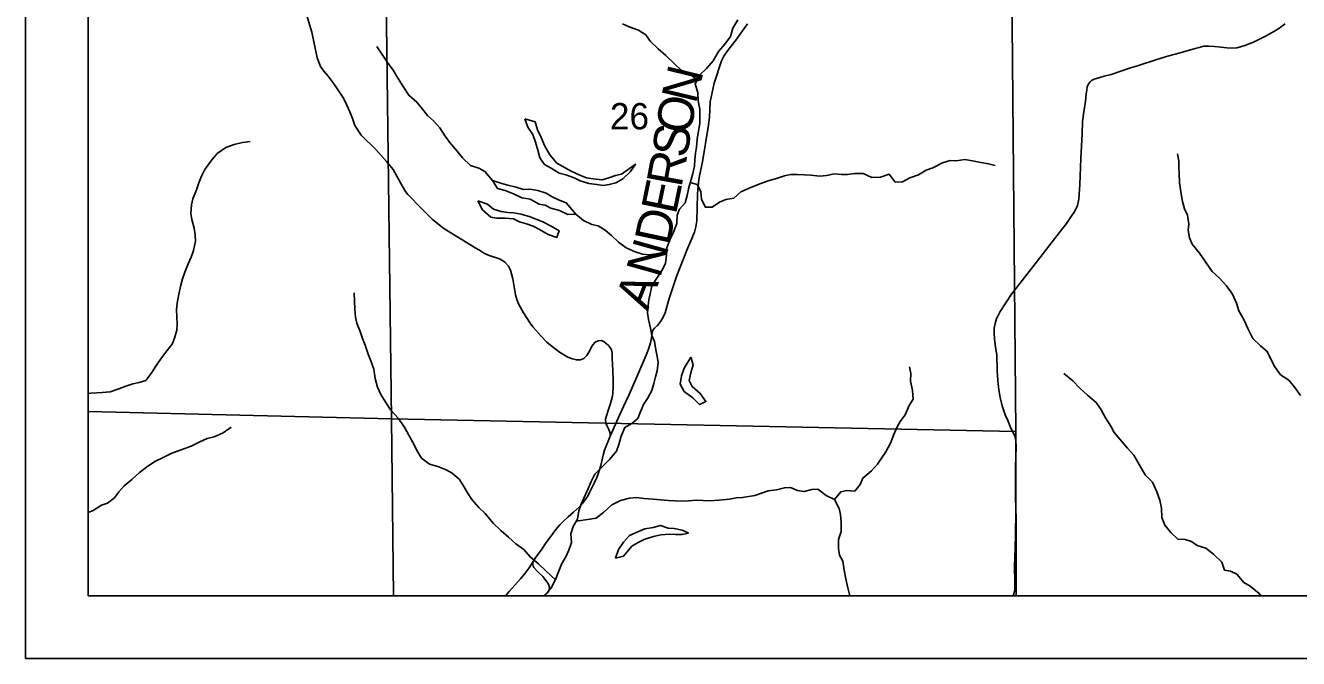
# Model space of a CAD drawing. Extents: x 0 to 34, y 0 to 22.
# Drawn here: x 2 to 4.027, y 14 to 15.007 of the extents above; entities that cross this region are included whole.
import ezdxf

# ---------------------------------------------------------------- set-up
doc = ezdxf.new("R2010")
doc.units = 0
for name, color, linetype in [('Default', 7, 'Continuous'), ('GM_X_Minor_Lake', 7, 'Continuous'), ('GM_X_Minor_River', 7, 'Continuous'), ('GM_X_Rail_Line', 7, 'Continuous'), ('GM_X_Section', 7, 'Continuous'), ('GM_X_Section_Text', 7, 'Continuous'), ('GM_X_Township_Road', 7, 'Continuous'), ('GM_X_Township_Road_Text', 7, 'Continuous'), ('SH_Cut_Line', 7, 'Continuous'), ('SH_Data', 7, 'Continuous')]:
    doc.layers.add(name, color=color, linetype=linetype)

msp = doc.modelspace()

# ---------------------------------------------------------------- linework, layer by layer
at = {"layer": 'Default'}
for points in [[(2.1, 15.3991), (2.1, 14.393), (2.5826, 14.3817), (2.5698, 15.3877)], [(2.1, 14.393), (2.1, 14.1), (2.5857, 14.1), (2.5826, 14.3817)], [(2.5857, 14.1), (3.5773, 14.1), (3.5764, 14.3611), (2.5826, 14.3817)]]:
    msp.add_lwpolyline(points, close=True, dxfattribs=at)
at = {"layer": 'GM_X_Minor_Lake'}
for points in [[(2.7949, 14.8587), (2.7995, 14.8455), (2.8075, 14.8338), (2.8117, 14.8216), (2.8155, 14.8088), (2.8189, 14.797), (2.8262, 14.7864), (2.8368, 14.7804), (2.8497, 14.7725), (2.8603, 14.7695), (2.8736, 14.765), (2.8831, 14.7601), (2.8967, 14.756), (2.9096, 14.7541), (2.9194, 14.753), (2.9293, 14.7542), (2.9399, 14.7572), (2.9512, 14.7633), (2.9629, 14.7747), (2.967, 14.7804)], [(2.967, 14.7804), (2.9712, 14.7865), (2.9614, 14.7796), (2.9489, 14.7709), (2.9391, 14.7686), (2.9289, 14.7651), (2.9183, 14.7617), (2.9035, 14.7636), (2.8929, 14.7647), (2.8823, 14.7692), (2.8686, 14.7756), (2.8591, 14.7809), (2.8459, 14.7884), (2.8345, 14.8016), (2.8268, 14.8152), (2.8211, 14.8289), (2.815, 14.8414), (2.8116, 14.8539), (2.7949, 14.8587)], [(2.7433, 14.7608), (2.7513, 14.7479), (2.7634, 14.7446), (2.7771, 14.7397), (2.79, 14.7333), (2.8036, 14.731), (2.8176, 14.7231), (2.8271, 14.7213), (2.8366, 14.7167), (2.8499, 14.713), (2.8635, 14.7066), (2.876, 14.707)], [(2.876, 14.707), (2.8608, 14.7252), (2.8487, 14.73), (2.8384, 14.7346), (2.8289, 14.7406), (2.8157, 14.7447), (2.8028, 14.747), (2.7929, 14.7466), (2.7812, 14.7499), (2.7679, 14.7533), (2.7581, 14.7559), (2.7433, 14.7608)], [(2.7203, 14.7285), (2.7275, 14.7141), (2.7408, 14.7024), (2.7506, 14.701), (2.7639, 14.701), (2.7768, 14.6999), (2.7863, 14.695), (2.7976, 14.6916), (2.8083, 14.6879), (2.8181, 14.6826), (2.8322, 14.6747), (2.8458, 14.6702), (2.8474, 14.6746)], [(2.8474, 14.6746), (2.8496, 14.6808), (2.8371, 14.6883), (2.8238, 14.6947), (2.8139, 14.6989), (2.8033, 14.703), (2.7893, 14.7071), (2.7775, 14.709), (2.768, 14.7097), (2.7574, 14.7116), (2.7453, 14.7153), (2.7354, 14.7233), (2.7203, 14.7285)], [(3.0593, 14.4798), (3.0487, 14.4623), (3.0446, 14.4498), (3.042, 14.4365), (3.0488, 14.4252), (3.0625, 14.415), (3.0731, 14.404), (3.0777, 14.4063)], [(3.0777, 14.4063), (3.0833, 14.409), (3.0742, 14.4215), (3.0613, 14.4328), (3.0567, 14.4427), (3.0593, 14.4544), (3.0627, 14.4673), (3.0593, 14.4798)], [(3.049, 14.2026), (3.0453, 14.2043), (3.0328, 14.2069), (3.0233, 14.2072), (3.0108, 14.2117), (2.9991, 14.2083), (2.9862, 14.2064), (2.9748, 14.2014), (2.9616, 14.196), (2.9521, 14.1854), (2.9442, 14.1736), (2.9393, 14.1596)], [(2.9393, 14.1596), (2.9522, 14.163), (2.9654, 14.1786), (2.9753, 14.1847), (2.9858, 14.1901), (3.0017, 14.1947), (3.0116, 14.1966), (3.0252, 14.1978), (3.0347, 14.1974), (3.0453, 14.1974), (3.0555, 14.1997), (3.049, 14.2026)]]:
    msp.add_lwpolyline(points, dxfattribs=at)
at = {"layer": 'GM_X_Minor_River'}
for points in [[(2.8887, 14.2553), (2.8947, 14.2678), (2.9007, 14.2815), (2.9064, 14.2933), (2.917, 14.3039), (2.9298, 14.3165), (2.9407, 14.3298), (2.9445, 14.3404), (2.9483, 14.354), (2.9543, 14.3677), (2.9652, 14.3742), (2.9751, 14.3822), (2.9788, 14.3916), (2.9841, 14.4045), (2.9905, 14.414), (2.9969, 14.4266), (3.0003, 14.4379), (3.0029, 14.4482), (3.0055, 14.458), (3.0074, 14.4713), (3.0058, 14.4808), (3.0035, 14.4914), (3.0012, 14.5043), (2.9974, 14.5141), (2.9951, 14.5258), (2.992, 14.5395), (2.9905, 14.5501), (2.9912, 14.5611), (2.9923, 14.5706), (2.9946, 14.5804), (2.9972, 14.5929), (3.0051, 14.6051), (3.0138, 14.618), (3.019, 14.629), (3.0205, 14.6411), (3.0209, 14.6536), (3.0258, 14.6665), (3.0314, 14.6787), (3.037, 14.6923), (3.0374, 14.7056), (3.0412, 14.7151), (3.0502, 14.7253), (3.0532, 14.7367), (3.0562, 14.7496), (3.0596, 14.7621), (3.0622, 14.7716), (3.0648, 14.7837), (3.0655, 14.794), (3.0667, 14.8042), (3.0681, 14.8137), (3.0692, 14.8266), (3.0707, 14.8364), (3.0733, 14.8512), (3.0737, 14.8611), (3.0733, 14.874), (3.071, 14.8876), (3.0702, 14.9005), (3.066, 14.9141), (3.0731, 14.9282), (3.0844, 14.9392), (3.095, 14.951), (3.1033, 14.9658), (3.1131, 14.9775), (3.1222, 14.9901), (3.1263, 15.0033), (3.1338, 15.0166)], [(3.0693, 14.9207), (3.0572, 14.9304), (3.0439, 14.9364), (3.0333, 14.9462), (3.0196, 14.9598), (3.0071, 14.97), (2.9945, 14.9825), (2.9877, 14.9923), (2.9759, 14.9999), (2.9611, 15.0051), (2.9505, 15.01)], [(3.0207, 14.6474), (3.0039, 14.6441), (2.9921, 14.6426), (2.9823, 14.6433), (2.9705, 14.6474), (2.9561, 14.6538), (2.9439, 14.6625), (2.9329, 14.6731), (2.9227, 14.6818), (2.9117, 14.6885), (2.9014, 14.6908), (2.8882, 14.6972), (2.876, 14.707), (2.8635, 14.7066), (2.8499, 14.713), (2.8366, 14.7167), (2.8271, 14.7213), (2.8176, 14.7231), (2.8036, 14.731), (2.79, 14.7333), (2.7771, 14.7397), (2.7634, 14.7446), (2.7513, 14.7479), (2.7433, 14.7608), (2.7315, 14.7748), (2.7216, 14.7804), (2.7084, 14.7846), (2.6958, 14.797), (2.6875, 14.8076), (2.6753, 14.8216), (2.6681, 14.8314), (2.6597, 14.8447), (2.6494, 14.8556), (2.6399, 14.8643), (2.6323, 14.8742), (2.6228, 14.8855), (2.6103, 14.8965), (2.6012, 14.9104), (2.592, 14.9248), (2.5856, 14.9365), (2.5761, 14.9483), (2.5593, 14.974)], [(2.1, 14.4215), (2.1045, 14.4224), (2.1223, 14.4236), (2.1351, 14.4244), (2.1488, 14.429), (2.1597, 14.4332), (2.1707, 14.437), (2.1809, 14.4393), (2.1915, 14.4423), (2.2013, 14.4553), (2.2077, 14.4655), (2.2153, 14.4769), (2.2251, 14.4898), (2.2338, 14.5001), (2.2375, 14.5096), (2.2409, 14.5228), (2.2413, 14.5323), (2.2409, 14.5437), (2.2404, 14.5554), (2.2415, 14.5653), (2.2442, 14.5797), (2.2471, 14.5941), (2.2498, 14.6043), (2.2539, 14.615), (2.2592, 14.6279), (2.2637, 14.6385), (2.2674, 14.6495), (2.2708, 14.6643), (2.2704, 14.6745), (2.2685, 14.6847), (2.2647, 14.6987), (2.2635, 14.7082), (2.2642, 14.7219), (2.2664, 14.7317), (2.2721, 14.7461), (2.2758, 14.7568), (2.2804, 14.7678), (2.2856, 14.7784), (2.2951, 14.7917), (2.3053, 14.8035), (2.3192, 14.813), (2.3321, 14.8179), (2.3457, 14.8214), (2.3579, 14.8226)], [(4.03, 14.4185), (4.0207, 14.4313), (4.0111, 14.4429), (3.9981, 14.4515), (3.9889, 14.4643), (3.9835, 14.4741), (3.9769, 14.4888), (3.9661, 14.4978), (3.9539, 14.5094), (3.9457, 14.5253), (3.9403, 14.5385), (3.9318, 14.5532), (3.9278, 14.5657), (3.9216, 14.5797), (3.912, 14.5932), (3.9001, 14.6056), (3.889, 14.6157), (3.8689, 14.6451), (3.8574, 14.6594), (3.8531, 14.6696), (3.8511, 14.6817), (3.8521, 14.6912), (3.8501, 14.7056), (3.845, 14.7158), (3.8418, 14.7275), (3.8394, 14.7426), (3.8373, 14.7574), (3.8368, 14.7718), (3.8363, 14.7813), (3.8362, 14.7915), (3.8338, 14.8033)], [(3.1559, 14.75), (3.1705, 14.7562), (3.1838, 14.7605), (3.194, 14.7633), (3.2083, 14.7684), (3.2181, 14.77), (3.2291, 14.7701), (3.2401, 14.7699), (3.2504, 14.7692), (3.2644, 14.7678), (3.275, 14.7687), (3.2879, 14.7711), (3.2993, 14.7701), (3.3087, 14.7702), (3.3201, 14.7719), (3.3334, 14.7716), (3.3471, 14.7657), (3.3611, 14.7662), (3.3747, 14.7709), (3.3847, 14.7578), (3.3961, 14.7587), (3.4077, 14.7652), (3.4217, 14.7699), (3.4338, 14.7769), (3.4443, 14.7808), (3.4598, 14.7889), (3.4723, 14.7925), (3.4817, 14.7918), (3.4954, 14.7939), (3.5075, 14.7921), (3.5208, 14.7896), (3.5333, 14.7875), (3.5436, 14.7845)], [(3.0583, 14.7573), (3.0691, 14.7546), (3.0752, 14.7432), (3.076, 14.7303), (3.0828, 14.7182), (3.093, 14.7183), (3.1048, 14.7263), (3.115, 14.7305), (3.1275, 14.7324), (3.1388, 14.7427), (3.1559, 14.75)], [(2.8437, 14.125), (2.8284, 14.1396), (2.8166, 14.1509), (2.8033, 14.1618), (2.7935, 14.1736), (2.7806, 14.1826), (2.7692, 14.1932), (2.757, 14.2038), (2.7445, 14.2155), (2.7316, 14.2306), (2.7217, 14.2404), (2.7107, 14.2529), (2.7038, 14.2635), (2.6977, 14.2737), (2.6909, 14.2851), (2.6791, 14.2952), (2.6696, 14.3005), (2.6563, 14.3054), (2.6431, 14.3095), (2.6305, 14.319), (2.6241, 14.3296), (2.6161, 14.3451), (2.6104, 14.3557), (2.6039, 14.367), (2.5936, 14.3818), (2.5814, 14.395), (2.5727, 14.409), (2.5658, 14.4203), (2.5605, 14.4321), (2.5567, 14.4457), (2.5547, 14.4605), (2.5498, 14.4737), (2.5456, 14.4843), (2.541, 14.4987), (2.5368, 14.5093), (2.5326, 14.5203), (2.5276, 14.5335), (2.5253, 14.5434), (2.5242, 14.5559), (2.5233, 14.5817)], [(3.2877, 14.2533), (3.2978, 14.2652), (3.3076, 14.2675), (3.3202, 14.2665), (3.3288, 14.2769), (3.3332, 14.2872), (3.3467, 14.2987), (3.3564, 14.3091), (3.3628, 14.3186), (3.3699, 14.3289), (3.3769, 14.3427), (3.3824, 14.3564), (3.3872, 14.3674), (3.3924, 14.377), (3.4003, 14.3877), (3.4066, 14.4025), (3.4129, 14.4129), (3.4123, 14.4265), (3.4091, 14.442), (3.4094, 14.4538), (3.4074, 14.464)], [(3.9668, 14.1), (3.9642, 14.1036), (3.9496, 14.1152), (3.9397, 14.1208), (3.9282, 14.1343), (3.9183, 14.1388), (3.9088, 14.1406), (3.9045, 14.1534), (3.8911, 14.1662), (3.8792, 14.1755), (3.8655, 14.1799), (3.856, 14.1863), (3.8461, 14.1892), (3.8347, 14.1899), (3.8232, 14.2003), (3.814, 14.212), (3.8089, 14.2245), (3.8087, 14.2393), (3.8059, 14.2518), (3.8009, 14.2654), (3.7942, 14.2808), (3.7827, 14.2925), (3.7727, 14.3087), (3.7642, 14.3234), (3.7542, 14.335), (3.7454, 14.3456), (3.7334, 14.3598), (3.728, 14.3696), (3.7195, 14.3832), (3.7122, 14.396), (3.7045, 14.4073), (3.6907, 14.4189), (3.6784, 14.4302), (3.6673, 14.4418), (3.6528, 14.4534)], [(2.1, 14.2325), (2.1076, 14.2356), (2.1209, 14.2439), (2.1307, 14.2474), (2.1417, 14.2557), (2.1489, 14.2652), (2.1572, 14.2747), (2.1693, 14.285), (2.1817, 14.296), (2.1946, 14.3063), (2.207, 14.3143), (2.218, 14.3196), (2.2328, 14.3269), (2.2464, 14.3315), (2.2638, 14.338), (2.2774, 14.3448), (2.2891, 14.3502), (2.3005, 14.3529), (2.3149, 14.359), (2.3277, 14.3681)], [(3.1613, 14.2595), (3.1822, 14.2666), (3.1954, 14.2686), (3.2083, 14.2718), (3.2177, 14.2723), (3.2292, 14.2675), (3.2394, 14.2657), (3.2519, 14.2692), (3.2614, 14.2693), (3.2744, 14.2592), (3.2877, 14.2533), (3.2951, 14.239), (3.2975, 14.2291), (3.2987, 14.217), (3.2985, 14.2022), (3.2945, 14.1893), (3.2943, 14.1752), (3.2959, 14.1646), (3.301, 14.1548), (3.3034, 14.1408), (3.3062, 14.1268), (3.309, 14.1124), (3.3126, 14.1)], [(2.8252, 14.1), (2.8259, 14.1005), (2.8364, 14.1115), (2.844, 14.1256), (2.8485, 14.1377), (2.8541, 14.1514), (2.8602, 14.162), (2.8651, 14.1726), (2.8692, 14.1848), (2.868, 14.1984), (2.8718, 14.2102), (2.8789, 14.2219), (2.8808, 14.2352), (2.8849, 14.2458), (2.8887, 14.2553)], [(2.8768, 14.2184), (2.8986, 14.2216), (2.9085, 14.2235), (2.9206, 14.2331), (2.9334, 14.2445), (2.9474, 14.2517), (2.9618, 14.2552), (2.9728, 14.2563), (2.9845, 14.2549), (2.9993, 14.2534), (3.011, 14.2527), (3.0239, 14.2516), (3.0345, 14.2512), (3.0444, 14.2505), (3.0554, 14.2509), (3.0679, 14.2521), (3.0789, 14.2513), (3.0887, 14.251), (3.1042, 14.2518), (3.1209, 14.2537), (3.1315, 14.2557), (3.1417, 14.2565), (3.1613, 14.2595)]]:
    msp.add_lwpolyline(points, dxfattribs=at)
at = {"layer": 'GM_X_Rail_Line'}
msp.add_lwpolyline([(2.1, 18.7171), (2.1, 14.1), (4.5781, 14.1), (4.5658, 14.9668), (4.5509, 15.5331), (4.5478, 16.582), (4.5489, 17.6578), (4.5474, 17.7028), (4.5429, 17.9404), (4.5419, 17.9684), (4.5402, 18.2851), (4.5408, 18.3763), (4.5397, 18.3961), (4.5397, 18.4045), (4.5399, 18.4424), (4.5403, 18.5054), (4.5462, 18.6416), (3.8456, 18.6615), (3.8442, 18.6615), (2.9234, 18.6945), (2.9222, 18.6946), (2.7892, 18.6993), (2.7864, 18.6994)], close=True, dxfattribs=at)
at = {"layer": 'GM_X_Section'}
msp.add_lwpolyline([(2.5698, 15.3877), (3.5676, 15.363), (3.5764, 14.3611), (2.5826, 14.3817)], close=True, dxfattribs=at)
at = {"layer": 'GM_X_Township_Road'}
for points in [[(2.4369, 15.0606), (2.4557, 14.9967), (2.4615, 14.9685), (2.4643, 14.956), (2.4697, 14.9422), (2.4749, 14.9348), (2.4821, 14.9265), (2.4898, 14.9161), (2.4968, 14.9061), (2.5062, 14.8917), (2.5118, 14.8808), (2.5162, 14.87), (2.5205, 14.8596), (2.5244, 14.848), (2.5343, 14.8327), (2.5577, 14.8103), (2.567, 14.8002), (2.5747, 14.7911), (2.5853, 14.778), (2.5995, 14.7524), (2.605, 14.7431), (2.6088, 14.7387), (2.6303, 14.716), (2.6481, 14.6985), (2.6658, 14.6844), (2.6774, 14.6774), (2.7101, 14.6573), (2.7161, 14.6537), (2.7227, 14.6496), (2.7309, 14.6448), (2.7381, 14.6414), (2.7448, 14.639), (2.7499, 14.6375), (2.7544, 14.636), (2.7595, 14.6336), (2.7633, 14.6306), (2.7688, 14.6242), (2.7721, 14.618), (2.7739, 14.6122), (2.7757, 14.604), (2.7799, 14.579), (2.7821, 14.5714), (2.7849, 14.5645), (2.793, 14.5499), (2.8033, 14.5336), (2.8078, 14.5281), (2.821, 14.5128), (2.8301, 14.5036), (2.8386, 14.4965), (2.8503, 14.4877), (2.8635, 14.4795), (2.8706, 14.4767), (2.877, 14.4751), (2.8836, 14.4754), (2.8891, 14.4776), (2.8937, 14.482), (2.8982, 14.4901), (2.9004, 14.4948), (2.9033, 14.4994), (2.9071, 14.5032), (2.9116, 14.5057), (2.9163, 14.5059), (2.9208, 14.5043), (2.9243, 14.5015), (2.9283, 14.4981), (2.931, 14.4949), (2.9331, 14.4913), (2.9342, 14.4857), (2.934, 14.4775), (2.9348, 14.4584), (2.9355, 14.443), (2.9356, 14.4323), (2.935, 14.4224), (2.9344, 14.4174), (2.9328, 14.4115), (2.9312, 14.406), (2.927, 14.3933), (2.9253, 14.3879), (2.9233, 14.3807), (2.9237, 14.3746), (2.9264, 14.3686), (2.9287, 14.3644), (2.9302, 14.3603), (2.9307, 14.3571), (2.9306, 14.3539)], [(2.826, 14.1), (2.831, 14.1046), (2.8339, 14.1089), (2.8344, 14.1131), (2.8326, 14.1186), (2.8291, 14.1236), (2.8236, 14.1303), (2.8154, 14.1382), (2.8091, 14.145), (2.808, 14.1468), (2.8075, 14.1489), (2.8077, 14.1514), (2.8082, 14.1543), (2.8092, 14.1559), (2.8116, 14.1597), (2.814, 14.1632), (2.8207, 14.1726), (2.8281, 14.1831), (2.8401, 14.1994), (2.8445, 14.2055), (2.8508, 14.2129), (2.8558, 14.218), (2.8637, 14.2254), (2.8723, 14.2327), (2.8822, 14.2415), (2.8863, 14.2461), (2.8922, 14.2539), (2.895, 14.2583), (2.8979, 14.264), (2.9057, 14.2799), (2.9094, 14.2881), (2.9123, 14.2955), (2.914, 14.3003), (2.9157, 14.3073), (2.9195, 14.3237), (2.922, 14.3317), (2.9306, 14.3539), (2.9455, 14.3872), (2.9518, 14.4011), (2.9608, 14.4204), (2.9734, 14.4481), (2.9881, 14.4828), (2.9919, 14.4924), (2.9948, 14.5022), (2.9964, 14.5101), (2.9984, 14.5212), (2.9992, 14.5231), (3.0015, 14.5255), (3.0061, 14.5302), (3.0114, 14.5369), (3.0154, 14.5432), (3.0181, 14.5501), (3.0244, 14.5711), (3.0363, 14.608), (3.0527, 14.6498), (3.0574, 14.6609), (3.0648, 14.6786), (3.0672, 14.6872), (3.0688, 14.6965), (3.0701, 14.7392), (3.0708, 14.752), (3.0719, 14.7617), (3.0738, 14.771), (3.0777, 14.7905), (3.0869, 14.8456), (3.0888, 14.8616), (3.0902, 14.8861), (3.0965, 14.9158), (3.1083, 14.9511), (3.1119, 14.9587), (3.1175, 14.9673), (3.1308, 14.9838), (3.1492, 15.0098)], [(4.0054, 15.0098), (3.9955, 15.0027), (3.9885, 14.9985), (3.9742, 14.9902), (3.9551, 14.981), (3.941, 14.9756), (3.9345, 14.9735), (3.9282, 14.9721), (3.9207, 14.9715), (3.9124, 14.9719), (3.9031, 14.973), (3.893, 14.9742), (3.8839, 14.9746), (3.8758, 14.9743), (3.8686, 14.9725), (3.8619, 14.9706), (3.842, 14.965), (3.8166, 14.9579), (3.7994, 14.9526), (3.7721, 14.9438), (3.7578, 14.9393), (3.7436, 14.9346), (3.7281, 14.9296), (3.7171, 14.9265), (3.7102, 14.9246), (3.7011, 14.9219), (3.6971, 14.9197), (3.6948, 14.9177), (3.6919, 14.9135), (3.6904, 14.9096), (3.6895, 14.9044), (3.6885, 14.8988), (3.6874, 14.8872), (3.685, 14.8701), (3.6828, 14.8545), (3.6821, 14.835), (3.6802, 14.7955), (3.6784, 14.7543), (3.6771, 14.731), (3.6746, 14.7208), (3.6706, 14.7121), (3.6649, 14.7035), (3.6571, 14.6925), (3.6421, 14.6728), (3.6112, 14.6328), (3.5696, 14.58), (3.5517, 14.552), (3.5484, 14.5457), (3.546, 14.5409), (3.5437, 14.5334), (3.5421, 14.5258), (3.5419, 14.5179), (3.5427, 14.5088), (3.5444, 14.4954), (3.5464, 14.4835), (3.5471, 14.458), (3.548, 14.4425), (3.5495, 14.4276), (3.5514, 14.4154), (3.5549, 14.4021), (3.5594, 14.3876), (3.5636, 14.3789), (3.5678, 14.3691), (3.5712, 14.3613), (3.575, 14.3545), (3.5766, 14.3469), (3.5771, 14.3371), (3.5762, 14.3049), (3.5763, 14.2638), (3.5768, 14.2326), (3.576, 14.1979), (3.5755, 14.175), (3.5747, 14.1473), (3.5751, 14.1209), (3.5749, 14.108), (3.5723, 14.1)], [(2.7642, 14.1), (2.7698, 14.1065), (2.7878, 14.1267), (2.7957, 14.1358), (2.8021, 14.1442), (2.8082, 14.1543)]]:
    msp.add_lwpolyline(points, dxfattribs=at)
at = {"layer": 'SH_Cut_Line'}
msp.add_lwpolyline([(2.1, 20.9), (2.1, 14.1), (4.5781, 14.1)], dxfattribs=at)
at = {"layer": 'SH_Data'}
for p, q in [((2, 21), (2, 14)), ((2.1, 20.9), (2.1, 14.1)), ((2.1, 14.1), (8.9, 14.1)), ((2.1, 14.1), (2.1, 14.1)), ((2, 14), (9, 14))]:
    msp.add_line(p, q, dxfattribs=at)

# ---------------------------------------------------------------- texts
at = {"layer": 'GM_X_Section_Text'}
msp.add_text('26', height=0.04186, rotation=0, dxfattribs=at).set_placement((2.9304, 14.8421))
at = {"layer": 'GM_X_Township_Road_Text'}
for s, rotation, p in [('N', 76.447, (3.067, 14.8813)), ('O', 80.5221, (3.059, 14.833)), ('S', 80.6239, (3.0528, 14.7952)), ('R', 79.692, (3.0442, 14.7483)), ('E', 78.3227, (3.0354, 14.7052)), ('D', 77.8845, (3.0248, 14.6559)), ('N', 74.332, (3.0103, 14.604)), ('A', 68.9089, (2.9905, 14.5518))]:
    msp.add_text(s, height=0.0568, rotation=rotation, dxfattribs=at).set_placement(p)

doc.saveas('drawing.dxf')
